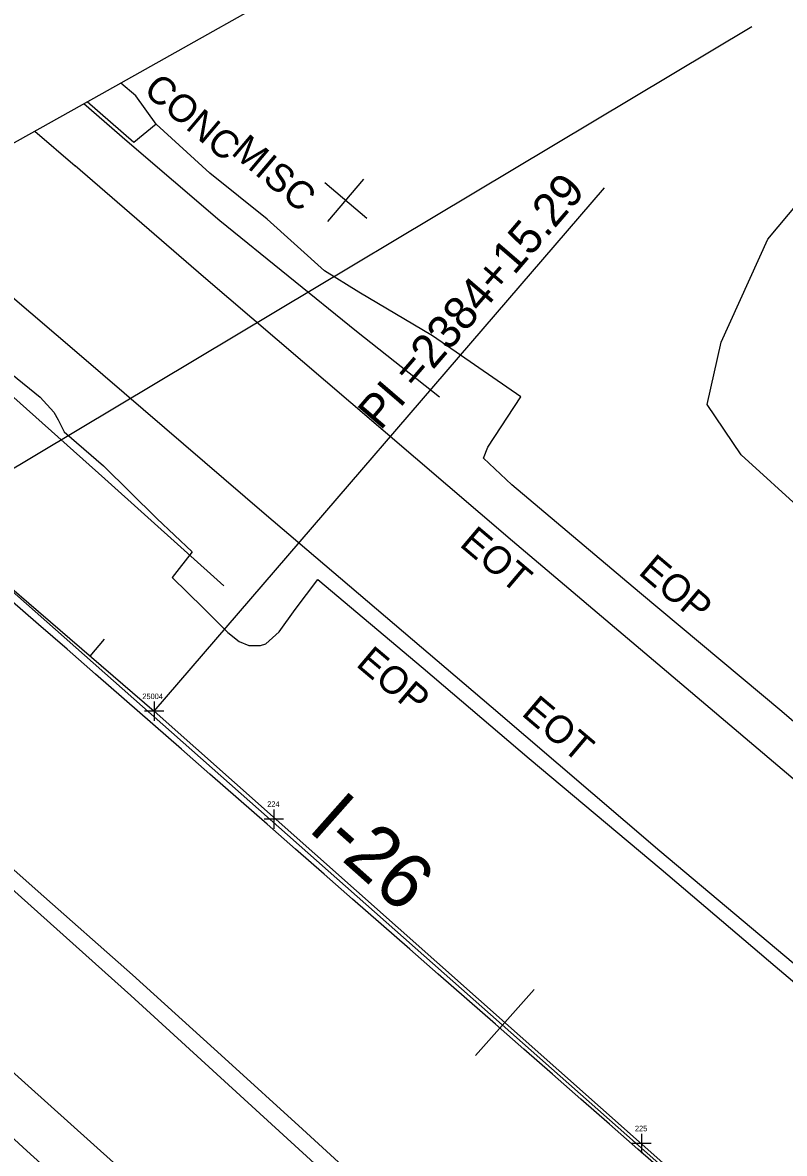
# Model space of a CAD drawing. Extents: x 2076109 to 2080761, y 592812 to 596750.
# Drawn here: x 2077381.1 to 2077518.8, y 595618.3 to 595822.6 of the extents above; entities that cross this region are included whole.
import ezdxf

# ---------------------------------------------------------------- set-up
doc = ezdxf.new("R2010")
doc.units = 0
for name, color, linetype in [('Default', 7, 'Continuous'), ('RD_EX_Bridge', 7, 'Continuous'), ('RD_EX_Conc', 7, 'Continuous'), ('RD_EX_Conc_txCode', 7, 'Continuous'), ('RD_EX_GuardRail', 7, 'Continuous'), ('RD_EX_Misc', 7, 'Continuous'), ('RD_EX_Misc_txCode', 7, 'Continuous'), ('RD_EX_Road', 7, 'Continuous'), ('RD_EX_Road_txCode', 7, 'Continuous'), ('RD_EX_UT', 7, 'Continuous'), ('RD_EX_VEG', 7, 'Continuous'), ('RD_HC_Cl', 7, 'Continuous'), ('RD_HC_Data', 7, 'Continuous'), ('RD_HC_Data_Tic', 7, 'Continuous'), ('RD_PD_ALT5_TX', 7, 'Continuous')]:
    doc.layers.add(name, color=color, linetype=linetype)

msp = doc.modelspace()

# ---------------------------------------------------------------- linework, layer by layer
at = {"layer": 'Default'}
for p, q in [((2077364.31, 595733.06), (2078453.96, 594769.07)), ((2077364.31, 595733.06), (2078453.96, 594769.07)), ((2077404.89, 595699.93), (2077404.89, 595696.43)), ((2077404.89, 595699.93), (2077404.89, 595696.43)), ((2077406.64, 595698.18), (2077403.14, 595698.18)), ((2077406.64, 595698.18), (2077403.14, 595698.18)), ((2077404.89, 595698.18), (2078420.27, 594797.03)), ((2077404.89, 595698.18), (2078420.27, 594797.03)), ((2077426.49, 595680.46), (2077426.49, 595676.96)), ((2077426.49, 595680.46), (2077426.49, 595676.96)), ((2077428.24, 595678.71), (2077424.74, 595678.71)), ((2077428.24, 595678.71), (2077424.74, 595678.71)), ((2077492.93, 595621.85), (2077492.93, 595618.35)), ((2077492.93, 595621.85), (2077492.93, 595618.35)), ((2077494.68, 595620.1), (2077491.18, 595620.1)), ((2077494.68, 595620.1), (2077491.18, 595620.1))]:
    msp.add_line(p, q, dxfattribs=at)
msp.add_arc((2035586.7, 547847.96), 63546.51, 48.5011873, 49.2923126, dxfattribs=at)
msp.add_arc((2035586.7, 547847.96), 63546.51, 48.5011873, 49.2923126, dxfattribs=at)
at = {"layer": 'RD_EX_Bridge'}
msp.add_lwpolyline([(2077182.69, 595725.56), (2077226.26, 595749.95), (2077278.63, 595779.43), (2077318.69, 595801.87), (2077370.98, 595831.15), (2077414.59, 595855.59), (2077438.98, 595834.26), (2077395.4, 595809.74), (2077342.89, 595780.4), (2077302.73, 595757.84), (2077250.38, 595728.31), (2077206.95, 595704.06)], close=True, dxfattribs=at)
msp.add_lwpolyline([(2077182.69, 595725.56), (2077226.26, 595749.95), (2077278.63, 595779.43), (2077318.69, 595801.87), (2077370.98, 595831.15), (2077414.59, 595855.59), (2077438.98, 595834.26), (2077395.4, 595809.74), (2077342.89, 595780.4), (2077302.73, 595757.84), (2077250.38, 595728.31), (2077206.95, 595704.06)], close=True, dxfattribs=at)
at = {"layer": 'RD_EX_Conc'}
for points in [[(2077401.56, 595809.39), (2077398.85, 595811.69)], [(2077401.56, 595809.39), (2077398.85, 595811.69)], [(2077405.25, 595804.28), (2077401.56, 595809.39)], [(2077405.25, 595804.28), (2077401.56, 595809.39)]]:
    msp.add_lwpolyline(points, dxfattribs=at)
at = {"layer": 'RD_EX_GuardRail'}
for points in [[(2077456.44, 595754.95), (2077441.45, 595766.81), (2077416.74, 595786.81), (2077400.01, 595801.14), (2077392.18, 595807.95)], [(2077456.44, 595754.95), (2077441.45, 595766.81), (2077416.74, 595786.81), (2077400.01, 595801.14), (2077392.18, 595807.95)], [(2077347.14, 595782.78), (2077350.32, 595780.06), (2077377.83, 595756.36), (2077395.95, 595740.2), (2077417.49, 595720.82)], [(2077347.14, 595782.78), (2077350.32, 595780.06), (2077377.83, 595756.36), (2077395.95, 595740.2), (2077417.49, 595720.82)]]:
    msp.add_lwpolyline(points, dxfattribs=at)
at = {"layer": 'RD_EX_Misc'}
for p, q in [((2077435.7, 595793.73), (2077443.33, 595787.27)), ((2077435.7, 595793.73), (2077443.33, 595787.27)), ((2077436.28, 595786.68), (2077442.74, 595794.32)), ((2077436.28, 595786.68), (2077442.74, 595794.32))]:
    msp.add_line(p, q, dxfattribs=at)
for points in [[(2077383.29, 595802.98), (2077390.58, 595796.7)], [(2077383.29, 595802.98), (2077390.58, 595796.7)], [(2077949.74, 595346.22), (2077917.12, 595371.24), (2077886.25, 595394.66), (2077855.54, 595418.26), (2077826.17, 595440.63), (2077793.37, 595466.01), (2077761.67, 595490.62), (2077722.71, 595521.26), (2077691.23, 595545.97), (2077665.74, 595566.25), (2077632.03, 595593.21), (2077582.35, 595633.88), (2077560.53, 595652.07), (2077526.26, 595680.98), (2077495.89, 595706.68), (2077469.6, 595728.93), (2077440.39, 595753.88), (2077413.8, 595776.66), (2077390.58, 595796.7)], [(2077949.74, 595346.22), (2077917.12, 595371.24), (2077886.25, 595394.66), (2077855.54, 595418.26), (2077826.17, 595440.63), (2077793.37, 595466.01), (2077761.67, 595490.62), (2077722.71, 595521.26), (2077691.23, 595545.97), (2077665.74, 595566.25), (2077632.03, 595593.21), (2077582.35, 595633.88), (2077560.53, 595652.07), (2077526.26, 595680.98), (2077495.89, 595706.68), (2077469.6, 595728.93), (2077440.39, 595753.88), (2077413.8, 595776.66), (2077390.58, 595796.7)], [(2077362.93, 595786.89), (2077392.15, 595761.97), (2077424.77, 595734), (2077441.81, 595719.44), (2077465.76, 595699.03), (2077496.26, 595672.94), (2077521.85, 595651.48), (2077549.58, 595628.1), (2077573.59, 595607.87), (2077599.85, 595586.33), (2077627.21, 595563.92), (2077661.18, 595537.05), (2077689.72, 595514.51), (2077716.09, 595493.76), (2077749.65, 595467.6), (2077783.36, 595441.51), (2077815.88, 595416.61), (2077850.74, 595389.82), (2077878.87, 595368.26), (2077915.16, 595340.49), (2077948.94, 595314.49)], [(2077362.93, 595786.89), (2077392.15, 595761.97), (2077424.77, 595734), (2077441.81, 595719.44), (2077465.76, 595699.03), (2077496.26, 595672.94), (2077521.85, 595651.48), (2077549.58, 595628.1), (2077573.59, 595607.87), (2077599.85, 595586.33), (2077627.21, 595563.92), (2077661.18, 595537.05), (2077689.72, 595514.51), (2077716.09, 595493.76), (2077749.65, 595467.6), (2077783.36, 595441.51), (2077815.88, 595416.61), (2077850.74, 595389.82), (2077878.87, 595368.26), (2077915.16, 595340.49), (2077948.94, 595314.49)], [(2077850.7, 595201.63), (2077820.53, 595232.8), (2077790.22, 595263.88), (2077762.8, 595291.76), (2077736.42, 595318.96), (2077709.92, 595346.36), (2077678.72, 595378.46), (2077649.91, 595408.22), (2077612.46, 595446.3), (2077577.19, 595481.07), (2077550.3, 595507.41), (2077509.12, 595546.77), (2077481.37, 595572.73), (2077443, 595608.1), (2077400.67, 595646.86), (2077373.88, 595670.82), (2077334.03, 595706.37), (2077304.56, 595732)], [(2077850.7, 595201.63), (2077820.53, 595232.8), (2077790.22, 595263.88), (2077762.8, 595291.76), (2077736.42, 595318.96), (2077709.92, 595346.36), (2077678.72, 595378.46), (2077649.91, 595408.22), (2077612.46, 595446.3), (2077577.19, 595481.07), (2077550.3, 595507.41), (2077509.12, 595546.77), (2077481.37, 595572.73), (2077443, 595608.1), (2077400.67, 595646.86), (2077373.88, 595670.82), (2077334.03, 595706.37), (2077304.56, 595732)], [(2077812.69, 595205.74), (2077779.15, 595240.73), (2077743.86, 595277.34), (2077707.16, 595314.93), (2077677.78, 595345.17), (2077641.95, 595381.51), (2077607.57, 595416.21), (2077570.67, 595452.82), (2077540.71, 595482.36), (2077500.4, 595521.29), (2077469.88, 595550.44), (2077431.8, 595585.6), (2077401.7, 595612.91), (2077373.73, 595637.96), (2077342.22, 595666.06), (2077323.28, 595683.05), (2077307.69, 595696.83), (2077294.47, 595708.58)], [(2077812.69, 595205.74), (2077779.15, 595240.73), (2077743.86, 595277.34), (2077707.16, 595314.93), (2077677.78, 595345.17), (2077641.95, 595381.51), (2077607.57, 595416.21), (2077570.67, 595452.82), (2077540.71, 595482.36), (2077500.4, 595521.29), (2077469.88, 595550.44), (2077431.8, 595585.6), (2077401.7, 595612.91), (2077373.73, 595637.96), (2077342.22, 595666.06), (2077323.28, 595683.05), (2077307.69, 595696.83), (2077294.47, 595708.58)]]:
    msp.add_lwpolyline(points, dxfattribs=at)
at = {"layer": 'RD_EX_Road'}
for points in [[(2077405.25, 595804.28), (2077401.21, 595800.92), (2077392.79, 595808.28)], [(2077405.25, 595804.28), (2077401.21, 595800.92), (2077392.79, 595808.28)], [(2077753.88, 595507.5), (2077725.13, 595529.95), (2077692.51, 595555.53), (2077660, 595581.25), (2077624.46, 595610.18), (2077590.24, 595637.95), (2077561.78, 595661.94), (2077534.99, 595683.83), (2077518.29, 595698.14), (2077492.56, 595719.65), (2077469.48, 595739.08), (2077464.38, 595743.91), (2077465.16, 595745.87), (2077471.12, 595754.97), (2077455.17, 595766.04), (2077441.89, 595773.92), (2077435.65, 595777.78), (2077425.27, 595787.12), (2077414.92, 595795.42), (2077405.25, 595804.28)], [(2077753.88, 595507.5), (2077725.13, 595529.95), (2077692.51, 595555.53), (2077660, 595581.25), (2077624.46, 595610.18), (2077590.24, 595637.95), (2077561.78, 595661.94), (2077534.99, 595683.83), (2077518.29, 595698.14), (2077492.56, 595719.65), (2077469.48, 595739.08), (2077464.38, 595743.91), (2077465.16, 595745.87), (2077471.12, 595754.97), (2077455.17, 595766.04), (2077441.89, 595773.92), (2077435.65, 595777.78), (2077425.27, 595787.12), (2077414.92, 595795.42), (2077405.25, 595804.28)], [(2077352.84, 595780.12), (2077367.9, 595768.16), (2077384.27, 595754.91), (2077386.73, 595752.23), (2077387.53, 595750.86), (2077388.64, 595748.64), (2077395.74, 595742.54), (2077405.35, 595732.98), (2077411.75, 595726.97), (2077408.1, 595722.38), (2077413.71, 595716.9), (2077418.18, 595712.39), (2077420.26, 595710.77), (2077422.01, 595710.08), (2077424.08, 595710.09), (2077425.05, 595710.37), (2077427.44, 595712.55), (2077430.35, 595716.54), (2077434.43, 595722.01), (2077453.49, 595705.97), (2077472.64, 595689.67), (2077496.48, 595669.68), (2077517.08, 595652.15), (2077543.34, 595629.88)], [(2077352.84, 595780.12), (2077367.9, 595768.16), (2077384.27, 595754.91), (2077386.73, 595752.23), (2077387.53, 595750.86), (2077388.64, 595748.64), (2077395.74, 595742.54), (2077405.35, 595732.98), (2077411.75, 595726.97), (2077408.1, 595722.38), (2077413.71, 595716.9), (2077418.18, 595712.39), (2077420.26, 595710.77), (2077422.01, 595710.08), (2077424.08, 595710.09), (2077425.05, 595710.37), (2077427.44, 595712.55), (2077430.35, 595716.54), (2077434.43, 595722.01), (2077453.49, 595705.97), (2077472.64, 595689.67), (2077496.48, 595669.68), (2077517.08, 595652.15), (2077543.34, 595629.88)], [(2077528.44, 595532.32), (2077507.93, 595551.7), (2077491.72, 595567.02), (2077467.24, 595590.18), (2077449.74, 595606.14), (2077431.68, 595622.71), (2077417.63, 595635.43), (2077400.96, 595650.59), (2077383.92, 595665.65), (2077365.24, 595682.19), (2077343.44, 595701.66), (2077326.52, 595716.21), (2077315.27, 595726.7), (2077317.91, 595731.12), (2077318.69, 595732.86), (2077319.09, 595734.63), (2077318.89, 595736.63), (2077318.61, 595737.93), (2077317.61, 595740.01), (2077315.19, 595742.84)], [(2077528.44, 595532.32), (2077507.93, 595551.7), (2077491.72, 595567.02), (2077467.24, 595590.18), (2077449.74, 595606.14), (2077431.68, 595622.71), (2077417.63, 595635.43), (2077400.96, 595650.59), (2077383.92, 595665.65), (2077365.24, 595682.19), (2077343.44, 595701.66), (2077326.52, 595716.21), (2077315.27, 595726.7), (2077317.91, 595731.12), (2077318.69, 595732.86), (2077319.09, 595734.63), (2077318.89, 595736.63), (2077318.61, 595737.93), (2077317.61, 595740.01), (2077315.19, 595742.84)], [(2077277.58, 595711.76), (2077294.44, 595696.44), (2077316.48, 595676.87), (2077339.86, 595656.39), (2077363.23, 595635.78), (2077381.85, 595618.74), (2077401.46, 595601.04), (2077426.38, 595578.58), (2077449.29, 595557.26), (2077472.1, 595535.89), (2077492.72, 595516.55), (2077515.1, 595494.99), (2077537.08, 595473.82), (2077562.41, 595448.47), (2077584.67, 595425.87), (2077605.91, 595404.49), (2077629.68, 595380.24), (2077656.48, 595352.83), (2077679.73, 595328.95), (2077700.7, 595307.57), (2077723.07, 595284.36), (2077743.1, 595263.78)], [(2077277.58, 595711.76), (2077294.44, 595696.44), (2077316.48, 595676.87), (2077339.86, 595656.39), (2077363.23, 595635.78), (2077381.85, 595618.74), (2077401.46, 595601.04), (2077426.38, 595578.58), (2077449.29, 595557.26), (2077472.1, 595535.89), (2077492.72, 595516.55), (2077515.1, 595494.99), (2077537.08, 595473.82), (2077562.41, 595448.47), (2077584.67, 595425.87), (2077605.91, 595404.49), (2077629.68, 595380.24), (2077656.48, 595352.83), (2077679.73, 595328.95), (2077700.7, 595307.57), (2077723.07, 595284.36), (2077743.1, 595263.78)]]:
    msp.add_lwpolyline(points, dxfattribs=at)
at = {"layer": 'RD_EX_UT'}
msp.add_line((2077214.8, 595643.67), (2077512.89, 595821.92), dxfattribs=at)
msp.add_line((2077214.8, 595643.67), (2077512.89, 595821.92), dxfattribs=at)
at = {"layer": 'RD_EX_VEG'}
msp.add_lwpolyline([(2077743.14, 595571.92), (2077714.37, 595589.83), (2077692.45, 595601.95), (2077669.32, 595619.14), (2077639, 595640.01), (2077619.76, 595654.64), (2077606.34, 595663.97), (2077589.56, 595675.42), (2077578.67, 595684.27), (2077551.96, 595709.63), (2077522.34, 595734.14), (2077510.92, 595744.54), (2077504.79, 595753.59), (2077507.34, 595764.85), (2077515.75, 595783.48), (2077537.58, 595809.49), (2077586.06, 595839.41)], dxfattribs=at)
msp.add_lwpolyline([(2077743.14, 595571.92), (2077714.37, 595589.83), (2077692.45, 595601.95), (2077669.32, 595619.14), (2077639, 595640.01), (2077619.76, 595654.64), (2077606.34, 595663.97), (2077589.56, 595675.42), (2077578.67, 595684.27), (2077551.96, 595709.63), (2077522.34, 595734.14), (2077510.92, 595744.54), (2077504.79, 595753.59), (2077507.34, 595764.85), (2077515.75, 595783.48), (2077537.58, 595809.49), (2077586.06, 595839.41)], dxfattribs=at)
at = {"layer": 'RD_HC_Cl'}
for p, q in [((2076186.59, 596746.26), (2077404.89, 595698.18)), ((2077404.89, 595698.18), (2077928.38, 595233.58)), ((2077404.89, 595698.18), (2077928.38, 595233.58))]:
    msp.add_line(p, q, dxfattribs=at)
at = {"layer": 'RD_HC_Data'}
msp.add_line((2077404.89, 595698.18), (2077486.26, 595792.77), dxfattribs=at)
msp.add_line((2077404.89, 595698.18), (2077486.26, 595792.77), dxfattribs=at)
at = {"layer": 'RD_HC_Data_Tic'}
for p, q in [((2077393.3, 595708.15), (2077395.91, 595711.19)), ((2077393.3, 595708.15), (2077395.91, 595711.19)), ((2077468.25, 595641.95), (2077473.56, 595647.94)), ((2077468.25, 595641.95), (2077473.56, 595647.94)), ((2077468.25, 595641.95), (2077462.94, 595635.97)), ((2077468.25, 595641.95), (2077462.94, 595635.97))]:
    msp.add_line(p, q, dxfattribs=at)

# ---------------------------------------------------------------- texts
at = {"layer": 'Default'}
for s, p in [('25004', (2077402.74, 595700.38)), ('25004', (2077402.74, 595700.38)), ('224', (2077425.31, 595680.91)), ('224', (2077425.31, 595680.91)), ('225', (2077491.75, 595622.3)), ('225', (2077491.75, 595622.3))]:
    msp.add_text(s, height=1, dxfattribs=at).set_placement(p)
at = {"layer": 'RD_EX_Conc_txCode'}
msp.add_text('CONC', height=5, rotation=319.7592, dxfattribs=at).set_placement((2077402.72, 595810.02))
msp.add_text('CONC', height=5, rotation=319.7592, dxfattribs=at).set_placement((2077402.72, 595810.02))
at = {"layer": 'RD_EX_Misc_txCode'}
for s, p in [(' MISC', (2077417.19, 595800.13)), (' MISC', (2077417.19, 595800.13)), ('EOT', (2077459.87, 595728.15)), ('EOT', (2077459.87, 595728.15)), ('EOT', (2077471.07, 595697.58)), ('EOT', (2077471.07, 595697.58))]:
    msp.add_text(s, height=5, rotation=319.7592, dxfattribs=at).set_placement(p)
at = {"layer": 'RD_EX_Road_txCode'}
for p in [(2077492.19, 595723.09), (2077492.19, 595723.09), (2077441.16, 595706.48), (2077441.16, 595706.48)]:
    msp.add_text('EOP', height=5, rotation=319.7592, dxfattribs=at).set_placement(p)
at = {"layer": 'RD_HC_Data'}
msp.add_text('PI =2384+15.29', height=6, rotation=49.2954, dxfattribs=at).set_placement((2077445.77, 595748.76))
msp.add_text('PI =2384+15.29', height=6, rotation=49.2954, dxfattribs=at).set_placement((2077445.77, 595748.76))
at = {"layer": 'RD_PD_ALT5_TX'}
msp.add_text('I-26', height=10, rotation=318.4105, dxfattribs=at).set_placement((2077432.45, 595676.79))
msp.add_text('I-26', height=10, rotation=318.4105, dxfattribs=at).set_placement((2077432.45, 595676.79))

doc.saveas('drawing.dxf')
